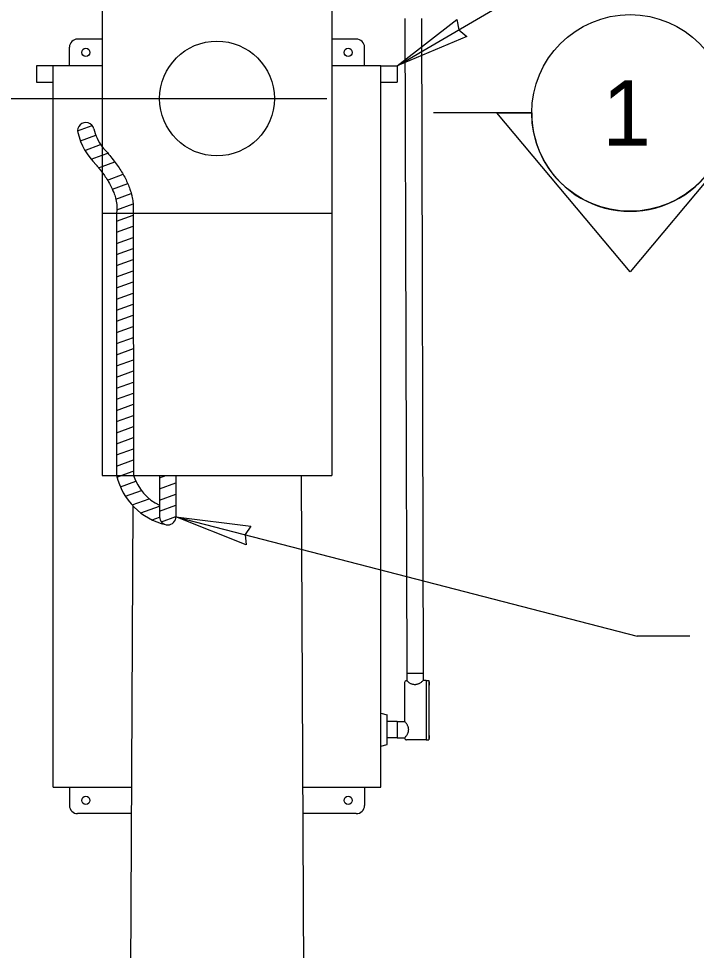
# Model space of a CAD drawing. Extents: x 99862 to 103151, y 100000 to 105076.
# Drawn here: x 101411.5 to 101618.2, y 100862.7 to 101146.8 of the extents above; entities that cross this region are included whole.
import ezdxf

# ---------------------------------------------------------------- set-up
doc = ezdxf.new("R2010")
doc.units = 0
for name, color, linetype in [('Level 1', 7, 'Continuous'), ('Level 15', 7, 'Continuous'), ('Level 20', 7, 'Continuous')]:
    doc.layers.add(name, color=color, linetype=linetype)

msp = doc.modelspace()

# ---------------------------------------------------------------- linework, layer by layer
at = {"layer": 'Level 1'}
for p, q in [((101437, 101157.47), (101437, 101007.47)), ((101507, 101157.47), (101507, 101007.47)), ((101529.34, 101146.83), (101529.86, 100947.15)), ((101534.34, 101146.83), (101534.86, 100947.15)), ((101437, 101140.6), (101429.5, 101140.6)), ((101514.5, 101140.6), (101507, 101140.6)), ((101427, 101132.47), (101427, 101138.1)), ((101517, 101132.47), (101517, 101138.1)), ((101422, 101132.47), (101417, 101132.47)), ((101417, 101132.47), (101417, 101127.47)), ((101422, 100912.47), (101422, 101132.47)), ((101437, 101132.47), (101422, 101132.47)), ((101522, 101132.47), (101507, 101132.47)), ((101522, 101132.47), (101527, 101132.47)), ((101522, 100912.47), (101522, 101132.47)), ((101527, 101132.47), (101527, 101127.47)), ((101417, 101127.47), (101422, 101127.47)), ((101522, 101127.47), (101527, 101127.47)), ((101429.5, 101112.63), (101433.93, 101114.24)), ((101430.35, 101109.54), (101435.05, 101111.26)), ((101431.72, 101106.65), (101436.52, 101108.4)), ((101433.6, 101103.94), (101437, 101105.18)), ((101437, 101105.18), (101438.7, 101105.8)), ((101435.88, 101101.37), (101437, 101101.78)), ((101437, 101101.78), (101440.81, 101103.17)), ((101438.56, 101097.61), (101443.34, 101099.36)), ((101440.09, 101094.78), (101444.8, 101096.5)), ((101441.15, 101091.77), (101445.87, 101093.49)), ((101441.47, 101088.49), (101446.44, 101090.3)), ((101437, 101087.47), (101507, 101087.47)), ((101441.4, 101087.47), (101441.4, 101007.47)), ((101441.4, 101085.07), (101446.4, 101086.9)), ((101446.4, 101087.47), (101446.58, 101007.47)), ((101441.4, 101081.67), (101446.41, 101083.5)), ((101441.4, 101078.28), (101446.42, 101080.11)), ((101441.4, 101074.88), (101446.43, 101076.72)), ((101441.4, 101071.49), (101446.43, 101073.32)), ((101441.4, 101068.09), (101446.44, 101069.93)), ((101441.4, 101064.69), (101446.45, 101066.54)), ((101441.4, 101061.3), (101446.46, 101063.14)), ((101441.4, 101057.9), (101446.46, 101059.75)), ((101441.4, 101054.51), (101446.47, 101056.36)), ((101441.4, 101051.11), (101446.48, 101052.97)), ((101441.4, 101047.72), (101446.49, 101049.57)), ((101441.4, 101044.32), (101446.49, 101046.18)), ((101441.4, 101040.92), (101446.5, 101042.79)), ((101441.4, 101037.53), (101446.51, 101039.39)), ((101441.4, 101034.13), (101446.52, 101036)), ((101441.4, 101030.74), (101446.53, 101032.61)), ((101441.4, 101027.34), (101446.53, 101029.21)), ((101441.4, 101023.94), (101446.54, 101025.82)), ((101441.4, 101020.55), (101446.55, 101022.43)), ((101441.4, 101017.15), (101446.56, 101019.03)), ((101441.4, 101013.76), (101446.56, 101015.64)), ((101441.4, 101010.36), (101446.57, 101012.25)), ((101437, 101007.47), (101507, 101007.47)), ((101441.52, 101007.01), (101442.79, 101007.47)), ((101442.79, 101007.47), (101446.4, 101008.79)), ((101454.5, 101007.47), (101454.5, 100994.91)), ((101454.5, 101006.77), (101456.42, 101007.47)), ((101459.5, 101007.47), (101459.5, 100994.91)), ((101497.68, 101007.47), (101498.78, 100762.47)), ((101442.55, 101003.99), (101447.26, 101005.71)), ((101454.5, 101003.37), (101459.5, 101005.2)), ((101444.07, 101001.15), (101448.93, 101002.92)), ((101454.5, 100999.98), (101459.5, 101001.81)), ((101446.11, 100998.5), (101451.34, 101000.41)), ((101454.5, 100996.58), (101459.5, 100998.41)), ((101446.29, 100998.31), (101445.23, 100762.47)), ((101448.76, 100996.07), (101454.5, 100998.17)), ((101452.24, 100993.94), (101454.51, 100994.77)), ((101455.03, 100993.38), (101459.5, 100995.01)), ((101529.22, 100944.33), (101529.22, 100932.47)), ((101529.83, 100944.93), (101529.86, 100944.93)), ((101529.86, 100947.15), (101534.86, 100947.15)), ((101529.86, 100947.15), (101529.86, 100944.93)), ((101534.86, 100947.15), (101534.86, 100944.93)), ((101535.77, 100944.93), (101534.86, 100944.93)), ((101535.77, 100944.93), (101535.77, 100926.85)), ((101535.77, 100944.93), (101536.61, 100944.93)), ((101536.61, 100944.93), (101536.61, 100926.85)), ((101536.71, 100944.62), (101536.61, 100944.62)), ((101536.71, 100943.45), (101536.61, 100943.45)), ((101536.76, 100944.08), (101536.76, 100943.99)), ((101536.81, 100944.08), (101536.76, 100944.08)), ((101536.81, 100943.99), (101536.76, 100943.99)), ((101522, 100934.97), (101523.92, 100934.53)), ((101523.92, 100925.41), (101523.92, 100934.53)), ((101527, 100932.47), (101523.92, 100932.47)), ((101527, 100932.47), (101527, 100927.47)), ((101527, 100932.47), (101529.22, 100932.47)), ((101527, 100927.47), (101523.92, 100927.47)), ((101527, 100927.47), (101529.22, 100927.47)), ((101529.22, 100927.49), (101529.22, 100927.45)), ((101536.71, 100928.33), (101536.61, 100928.33)), ((101536.76, 100927.8), (101536.76, 100927.7)), ((101536.81, 100927.8), (101536.76, 100927.8)), ((101536.81, 100927.7), (101536.76, 100927.7)), ((101522, 100924.97), (101523.92, 100925.41)), ((101535.77, 100926.85), (101529.83, 100926.85)), ((101535.77, 100926.85), (101536.61, 100926.85)), ((101536.71, 100927.16), (101536.61, 100927.16)), ((101422, 100912.47), (101445.9, 100912.47)), ((101427, 100912.47), (101427, 100906.85)), ((101498.11, 100912.47), (101522, 100912.47)), ((101517, 100912.47), (101517, 100906.85)), ((101445.87, 100904.35), (101429.5, 100904.35)), ((101514.5, 100904.35), (101498.14, 100904.35))]:
    msp.add_line(p, q, dxfattribs=at)
for centre, radius in [((101432, 101136.53), 1.25), ((101472, 101122.47), 17.5), ((101512, 101136.53), 1.25), ((101432, 100908.41), 1.25), ((101512, 100908.41), 1.25)]:
    msp.add_circle(centre, radius, dxfattribs=at)
for centre, radius, start, end in [((101429.5, 101138.1), 2.5, 90, 180), ((101514.5, 101138.1), 2.5, 0, 90), ((101432, 101112.65), 2.5, 13.2051, 194.6483), ((101449.04, 101116.65), 20, 193.0247, 225.8971), ((101449.04, 101116.65), 15, 193.2051, 216.6276), ((101460.89, 101011.98), 20, 193.0247, 256.8372), ((101460.89, 101011.98), 15, 197.4873, 244.8142), ((101457, 100994.91), 2.5, 180, 360), ((101529.83, 100944.33), 0.604, 90, 180), ((101535.09, 100944.04), 1.72, 1.5555, 19.8358), ((101535.09, 100944.04), 1.72, 340.1642, 358.4445), ((101529.83, 100927.45), 0.604, 180, 270), ((101535.09, 100927.75), 1.72, 1.5555, 19.8358), ((101535.09, 100927.75), 1.72, 340.1642, 358.4445), ((101429.5, 100906.85), 2.5, 180, 270), ((101514.5, 100906.85), 2.5, 270, 360)]:
    msp.add_arc(centre, radius, start, end, dxfattribs=at)
for points, degree in [([(101437, 101107.7), (101447.4, 101096.5), (101446.4, 101087.47)], 2), ([(101435.12, 101102.29), (101435.8, 101101.48), (101436.42, 101100.7), (101437, 101099.91)], 2), ([(101437, 101099.91), (101437.14, 101099.72), (101437.28, 101099.53), (101438.52, 101097.78), (101439.38, 101096.3), (101440.65, 101093.57), (101441.06, 101092.32), (101441.5, 101090.03), (101441.54, 101089), (101441.4, 101087.47)], 3), ([(101534.86, 100944.93), (101532.36, 100942.43), (101529.86, 100944.93)], 2), ([(101529.22, 100927.47), (101531.72, 100929.97), (101529.22, 100932.47)], 2)]:
    msp.add_open_spline(points, degree=degree, dxfattribs=at)
at = {"layer": 'Level 15'}
for p, q in [((101527, 101132.47), (101592.18, 101170.59)), ((101217.5, 101122.47), (101505.5, 101122.47)), ((101459.5, 100994.91), (101600.18, 100958.46)), ((101616.18, 100958.46), (101600.18, 100958.46))]:
    msp.add_line(p, q, dxfattribs=at)
for points in [[(101527, 101132.47), (101545.2, 101146.57), (101545.8, 101143.46), (101548.22, 101141.42)], [(101459.5, 100994.91), (101482.35, 100992.07), (101480.58, 100989.45), (101480.86, 100986.3)]]:
    msp.add_lwpolyline(points, close=True, dxfattribs=at)
at = {"layer": 'Level 20'}
for p, q in [((101568, 101118.06), (101538, 101118.06)), ((101557.4, 101118.06), (101568, 101118.06)), ((101598, 101069.59), (101557.4, 101118.06)), ((101638.61, 101118.06), (101598, 101069.59))]:
    msp.add_line(p, q, dxfattribs=at)
msp.add_circle((101598, 101118.06), 30, dxfattribs=at)
msp.add_arc((101598, 101118.06), 30, 179.9978, 0.0022, dxfattribs=at)

# ---------------------------------------------------------------- texts
msp.add_text('1', height=20, dxfattribs=at).set_placement((101589.54, 101108.06))

doc.saveas('drawing.dxf')
